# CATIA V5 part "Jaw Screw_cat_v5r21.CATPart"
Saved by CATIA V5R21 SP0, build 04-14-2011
Part number: Jaw Screw
Bounding box of the stored display mesh (mm): x -9 to 9, y 0 to 138, z -8.948 to 8.97
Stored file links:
  D:\CATIA V5R21 E-RESOURCES\CATIA-V5R21\catia-v5r21-Tut\c13-catia-v5r21-tut\c13-catia-v5r21-tut02\Bench Vice\Jaw Screw_cat_v5r21.CATPart
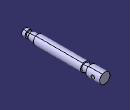
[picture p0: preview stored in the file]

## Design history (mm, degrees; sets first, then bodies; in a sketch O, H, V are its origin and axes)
Body1 (main body)
  Sketch1 on yz-plane, origin (0, 0, 0), H (0, 1, 0), V (0, 0, 1)
    line L1 (0, 0) -> (0, 6)
    line L2 (0, 6) -> (6, 6)
    line L3 (6, 6) -> (6, 4)
    line L4 (6, 4) -> (11, 4)
    line L5 (11, 4) -> (11, 6)
    point P5 (11, 6)
    line L6 (11, 6) -> (22, 6)
    line L7 (22, 6) -> (22, 8)
    line L8 (22, 8) -> (104, 8)
    line L9 (104, 8) -> (104, 6)
    point P9 (104, 6)
    line L10 (104, 6) -> (114, 6)
    line L11 (114, 6) -> (114, 9)
    line L12 (114, 9) -> (138, 9)
    line L13 (138, 9) -> (138, 0)
    point P13 (138, 0)
    line L14 (138, 0) -> (0, 0)
    distance L2 L14 = 6
    distance L8 L14 = 8
    distance L12 L14 = 9
    length L2 = 6
    length L4 = 5
    length L8 = 82
    length L10 = 10
    length L12 = 24
    length L14 = 138
    distance L4 L14 = 4
    vertical: L1 V, L3 V, L5 V, L7 V, L9 V, L11 V, L13 V
    horizontal: L2 H, L4 H, L6 H, L8 H, L10 H, L12 H, L14 H
    coincidence: P5 L2, P9 L6, P13 H
  Shaft1: profile Sketch1, axis edge of Sketch1, angle 360
  Sketch2 on yz-plane, origin (0, 0, 0), H (0, 1, 0), V (0, 0, 1)
    circle A1 centre (126, 0) radius 3
    point P1 (126, 0)
    radius A1 = 3
    distance P1 V = 126
    coincidence: P1 H
  Pocket1: profile Sketch2, direction (-1, 0, 0), length 20, mirrored extent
